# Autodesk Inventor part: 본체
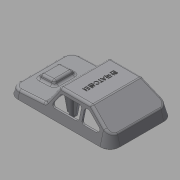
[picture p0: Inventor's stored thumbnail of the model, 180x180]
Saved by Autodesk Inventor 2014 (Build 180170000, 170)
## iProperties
Created: 2015-05
Part Number: 본체
Material: Generic
Document SubType Name: Modeling
Designer: Administrator
Density: 1 g/cm^3
Appearance: Default
Author: Administrator
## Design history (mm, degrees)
sketch "스케치1"
  geometry: L1 (-49, -38)-(49, -38); L2 (61, -26)-(61, 26); L3 (49, 38)-(-49, 38); L4 (-61, 26)-(-61, -26); L5 (-61, -38)-(61, 38); L6 (61, -38)-(-61, 38); A1 r 12 centre (-49, 26) between (-49, 38) and (-61, 26); A2 r 12 centre (-49, -26) between (-61, -26) and (-49, -38); A3 r 12 centre (49, -26) between (49, -38) and (61, -26); A4 r 12 centre (49, 26) between (61, 26) and (49, 38); 3 further points
  constraints: 12 end point, 8 point on circle, 8 point on line, 8 tangent, 4 centre point, 3 equal radius, 3 midpoint, 2 parallel, 1 coincident, 1 horizontal, 1 perpendicular
  dimensions: "d0" = 122 distance of L5.end L6.end; "d1" = 76 distance of L6.start L5.end; "d2" = 12 radius of A1
extrude "돌출1" new body sketch "스케치1" distance "d3" = 30; taper "d4" = -15 deg
sketch "스케치2"
  geometry: L1 (49, 30)-(-49, 30) reference; L2 (-61, 0)-(-52.962, 30) reference; L3 (49, 0)-(-49, 0) reference; L4 (-61, 0)-(-49, 0) reference; L5 (-52.962, 30)-(-49, 30) reference; L6 (-31, 30)-(-61, 10); L7 (-61, 10)-(-61, 30); L8 (-61, 30)-(-31, 30); 1 further point
  constraints: 6 end point, 2 perpendicular, 1 collinear, 1 vertical alignment
  dimensions: "d5" = 20 distance of L6.end L7.end; "d6" = 30 distance of L7.end L6.start
extrude "돌출2" cut sketch "스케치2" stored distance "d7" = 30; taper "d8" = 0 deg
sketch "스케치3"
  geometry: L1 (49, 0)-(61, 0) reference; L2 (61, 0)-(52.962, 30) reference; L3 (49, 30)-(-31, 30) reference; L4 (49, 30)-(52.962, 30) reference; L5 (49, 0)-(-49, 0) reference; L6 (61, 8)-(19, 10.201); L7 (19, 10.201)-(6.628, 30); L8 (6.628, 30)-(61, 30); L9 (61, 30)-(61, 8); 1 further point
  constraints: 8 end point, 1 collinear, 1 parallel, 1 perpendicular, 1 vertical alignment
  dimensions: "d10" = 125 deg angle of L7 L6; "d11" = 3 deg angle of L6 L5; "d12" = 8 distance of L6.start L1.end; "d13" = 42 horizontal distance of L6.end L6.start
extrude "돌출3" cut sketch "스케치3" stored distance "d14" = 30; taper "d15" = 0 deg
sketch "스케치4"
  geometry: L1 (-42.476, 9.267)-(-42.476, 61.267) reference; L2 (-31.476, 48.267)-(-11.476, 48.267); L3 (-11.476, 48.267)-(-11.476, 22.267); L4 (-11.476, 22.267)-(-31.476, 22.267); L5 (-31.476, 22.267)-(-31.476, 48.267); 3 further points
  constraints: 8 end point, 2 midpoint, 2 parallel, 1 horizontal, 1 horizontal alignment, 1 perpendicular
  dimensions: "d16" = 26 distance of L2.end L3.end; "d17" = 20 distance of L3.end L4.end; "d18" = 11 distance between parallel lines of L1 L5
extrude "돌출4" join sketch "스케치4" distance "d19" = 5; taper "d20" = -20 deg
fillet "모깎기1" dims "d21" = 3
fillet "모깎기2" dims "d22" = 3
fillet "모깎기3" dims "d23" = 3
fillet "모깎기4" dims "d24" = 3
feature "쉘1" dims "d25" = 2
sketch "스케치5"
  geometry: L1 (-49, 35.929)-(49, 35.929) reference; L2 (58.929, 26)-(58.929, -26) reference; L3 (49, -35.929)-(-49, -35.929) reference; L4 (-58.929, -26)-(-58.929, 26) reference; L5 (49, 36.929)-(-49, 36.929); L6 (-59.929, 26)-(-59.929, -26); L7 (-49, -36.929)-(49, -36.929); L8 (59.929, -26)-(59.929, 26); A1 r 9.929 centre (49, 26) between (58.929, 26) and (49, 35.929) reference; A2 r 9.929 centre (49, -26) between (49, -35.929) and (58.929, -26) reference; A3 r 9.929 centre (-49, -26) between (-58.929, -26) and (-49, -35.929) reference; A4 r 9.929 centre (-49, 26) between (-49, 35.929) and (-58.929, 26) reference; A5 r 10.929 centre (-49, 26) between (-49, 36.929) and (-59.929, 26); A6 r 10.929 centre (-49, -26) between (-59.929, -26) and (-49, -36.929); A7 r 10.929 centre (49, -26) between (49, -36.929) and (59.929, -26); A8 r 10.929 centre (49, 26) between (59.929, 26) and (49, 36.929); 1 further point
  constraints: 8 end point, 8 point on circle, 4 centre point, 7 other
  dimensions: "d26" = 1 distance between parallel lines of L5 L1
extrude "돌출5" join sketch "스케치5" distance "d27" = 1; taper "d28" = 0 deg
sketch "스케치6"
  geometry: L1 (18.172, 11.526)-(7.51, 28.59) reference; L2 (4.965, 30)-(-30.092, 30) reference; L3 (-31.756, 29.496)-(-50.664, 16.891) reference; L4 (10.362, 14.59)-(4.738, 23.59); L5 (2.194, 25)-(-17.77, 25); L6 (-20.77, 13)-(-20.77, 22); L7 (7.818, 10)-(-17.77, 10); L8 (-30.242, 24.496)-(-43.742, 15.496); L9 (-26.986, 25)-(-28.578, 25); L10 (-23.986, 22)-(-23.986, 13); L11 (-26.986, 10)-(-42.078, 10); A1 r 3 centre (7.818, 13) between (7.818, 10) and (10.362, 14.59); A2 r 3 centre (2.194, 22) between (4.738, 23.59) and (2.194, 25); A3 r 3 centre (-17.77, 22) between (-17.77, 25) and (-20.77, 22); A4 r 3 centre (-17.77, 13) between (-20.77, 13) and (-17.77, 10); A5 r 3 centre (-26.986, 13) between (-26.986, 10) and (-23.986, 13); A6 r 3 centre (-26.986, 22) between (-23.986, 22) and (-26.986, 25); A7 r 3 centre (-28.578, 22) between (-28.578, 25) and (-30.242, 24.496); A8 r 3 centre (-42.078, 13) between (-43.742, 15.496) and (-42.078, 10); 7 further points
  constraints: 16 end point, 16 point on circle, 16 tangent, 12 point on line, 8 centre point, 7 equal radius, 5 parallel, 3 perpendicular
  dimensions: "d29" = 5 distance between parallel lines of L2 L5; "d30" = 5 distance between parallel lines of L1 L4; "d31" = 34 distance of point (13.23, 10) point (-20.77, 10); "d32" = 15 distance of point (-20.77, 10) point (-20.77, 25); "d33" = 5 distance between parallel lines of L3 L8; "d34" = 5 distance between parallel lines of L2 L9; "d35" = 15 distance of point (-23.986, 25) point (-23.986, 10); "d36" = 28 distance of point (-23.986, 10) point (-51.986, 10); "d37" = 3 radius of A1
extrude "돌출6" cut sketch "스케치6" stored distance "d38" = 1; taper "d39" = 0 deg
node "작업 평면1"
sketch "스케치7"
  geometry: A1 r 4 centre (21, 0) between (25, 0) and (17, 0); A2 r 4 centre (10, 0) between (14, 0) and (6, 0); A3 r 4 centre (-10, 0) between (-6, 0) and (-14, 0); A4 r 4 centre (-21, 0) between (-17, 0) and (-25, 0); 4 further points
  constraints: 8 point on circle, 4 centre point, 4 horizontal alignment, 14 other
  dimensions: "d41" = 8 diameter of A1; "d42" = 8 diameter of A2; "d43" = 8 diameter of A3; "d44" = 8 diameter of A4; "d45" = 10 distance of A2.centre point (0, 0); "d46" = 20 distance of A3.centre A2.centre; "d47" = 11 distance of A2.centre A1.centre; "d48" = 11 distance of A4.centre A3.centre
extrude "돌출7" join sketch "스케치7" stored distance "d49" = 1; taper "d50" = 0 deg
chamfer "모따기1" distance "d51" = 1; stored, may be unused: second distance "d52" = 2, angle "d53" = 45 deg
sketch "스케치8"
  geometry: C1 r 3 at (-40, 0); C2 r 3 at (40, 0); C3 r 3 at (0, 22); C4 r 3 at (0, -22); 1 further point
  constraints: 4 centre point, 2 horizontal alignment, 2 vertical alignment
  dimensions: "d54" = 6 diameter of C1; "d55" = 6 diameter of C2; "d56" = 6 diameter of C3; "d57" = 6 diameter of C4; "d58" = 40 distance of point (0, 0) C1.centre; "d59" = 40 distance of C2.centre point (0, 0); "d60" = 22 distance of C3.centre point (0, 0); "d61" = 22 distance of point (0, 0) C4.centre
extrude "돌출8" join sketch "스케치8" stored distance "d62" = 1; taper "d63" = 2 deg
node "작업 평면2"
sketch "스케치9"
  geometry: L1 (-45, -1)-(-35, -1); L2 (-35, -1)-(-35, 1); L3 (-35, 1)-(-45, 1); L4 (-45, 1)-(-45, -1); L5 (-45, -1)-(-35, 1); L6 (-35, -1)-(-45, 1); L7 (-5, 21)-(5, 21); L8 (5, 21)-(5, 23); L9 (5, 23)-(-5, 23); L10 (-5, 23)-(-5, 21); L11 (-5, 21)-(5, 23); L12 (5, 21)-(-5, 23); L13 (35, -1)-(45, -1); L14 (45, -1)-(45, 1); L15 (45, 1)-(35, 1); L16 (35, 1)-(35, -1); L17 (35, -1)-(45, 1); L18 (45, -1)-(35, 1); L19 (-5, -23)-(5, -23); L20 (5, -23)-(5, -21); L21 (5, -21)-(-5, -21); L22 (-5, -21)-(-5, -23); L23 (-5, -23)-(5, -21); L24 (5, -23)-(-5, -21); C1 r 3 at (-40, 0) reference; C2 r 3 at (0, 22) reference; C3 r 3 at (40, 0) reference; C4 r 3 at (0, -22) reference; 1 further point
  constraints: 48 end point, 8 midpoint, 8 parallel, 4 horizontal, 4 perpendicular
  dimensions: "d65" = 10 distance of L1.start L1.end; "d66" = 2 distance of L1.end L2.end; "d67" = 10 distance of L7.start L7.end; "d68" = 2 distance of L7.end L8.end; "d69" = 10 distance of L19.start L19.end; "d70" = 2 distance of L19.end L20.end; "d71" = 10 distance of L13.start L13.end; "d72" = 2 distance of L13.end L14.end
extrude "돌출9" join sketch "스케치9" stored distance "d73" = 1; taper "d74" = 2.5 deg
sketch "스케치11"
  geometry: L1 (45, 2)-(45.429, 11.82) reference; L2 (35, 2)-(34.546, 12.39) reference; L3 (43, 0)-(43.07, 2) reference; L4 (37, 0)-(36.93, 2) reference; L5 (46.675, 11.755)-(34.533, 12.391) reference; L6 (47.906, 9.978)-(47.579, 11.049) reference; L7 (45, 2)-(46.72, 11.753); L8 (45.429, 11.82)-(46.72, 11.753); L9 (-49, 0)-(49, 0) reference; L10 (35, 2)-(33.155, 12.463); L11 (34.546, 12.39)-(33.155, 12.463); A1 r 1 centre (46.623, 10.756) between (47.579, 11.049) and (46.675, 11.755) reference; A2 r 5 centre (52.688, 11.44) between (47.906, 9.978) and (52.426, 6.447) reference; 1 further point
  constraints: 8 end point, 3 collinear, 1 point on line
  dimensions: "d76" = 80 deg angle of L7 L9; "d82" = 80 deg angle of L10 L9
extrude "돌출10" join sketch "스케치11" stored distance "d77" = 1; taper "d78" = 0 deg
sketch "스케치12"
  geometry: L1 (-45, 2)-(-46.719, 11.752) reference; L2 (-45.429, 11.82)-(-45, 2) reference; L3 (-46.675, 11.755)-(-45.429, 11.82) reference; A1 r 1 centre (-46.623, 10.756) between (-46.675, 11.755) and (-46.719, 11.752) reference; 1 further point
extrude "돌출11" join sketch "스케치12" stored distance "d79" = 1; taper "d80" = 0 deg
extrude "돌출12" join sketch "스케치11" stored distance "d83" = 1; taper "d84" = 0 deg
extrude "돌출13" join sketch "스케치11" stored distance "d85" = 1; taper "d86" = 0 deg
sketch "스케치13"
  geometry: L1 (-45, 2)-(-45.69, 17.803) reference; L2 (-35, 2)-(-33.969, 25.617) reference; L3 (-35, 2)-(-37.098, 2) reference; L4 (-42.902, 2)-(-45, 2) reference; L5 (49, 0)-(-49, 0) reference; L6 (-49.555, 15.226)-(-30.646, 27.832) reference; L7 (-45, 2)-(-47.566, 16.552); L8 (-35, 2)-(-30.426, 27.943); L9 (-30.092, 28)-(4.965, 28) reference; A1 r 1 centre (-30.092, 27) between (-30.092, 28) and (-30.646, 27.832) reference; 1 further point
  constraints: 4 end point, 1 point on circle, 1 point on line
  dimensions: "d87" = 80 deg angle of L8 L5; "d88" = 80 deg angle of L7 L5
extrude "돌출14" join sketch "스케치13" stored distance "d89" = 1; taper "d90" = 0 deg
extrude "돌출15" join sketch "스케치13" stored distance "d91" = 1; taper "d92" = 0 deg
extrude "돌출16" join sketch "스케치13" stored distance "d93" = 1; taper "d94" = 0 deg
extrude "돌출17" join sketch "스케치13" stored distance "d95" = 1; taper "d96" = 0 deg
node "작업 평면4"
sketch "스케치14"
  geometry: L1 (16.476, 10.466)-(5.813, 27.53) reference; L2 (4.965, 28)-(-30.092, 28) reference; L3 (-5, 2)-(-6.135, 28) reference; L4 (5, 2)-(6.095, 27.079) reference; L5 (-49, 0)-(49, 0) reference; L6 (5, 2)-(8.69, 22.927); L7 (-5, 2)-(-9.585, 28); 1 further point
  constraints: 4 end point, 2 point on line
  dimensions: "d98" = 80 deg angle of L6 L5; "d99" = 80 deg angle of L5 L7
extrude "돌출18" join sketch "스케치14" stored distance "d100" = 1; taper "d101" = 0 deg
extrude "돌출19" join sketch "스케치14" stored distance "d102" = 1; taper "d103" = 0 deg
extrude "돌출20" join sketch "스케치14" stored distance "d104" = 1; taper "d105" = 0 deg
extrude "돌출21" join sketch "스케치14" stored distance "d106" = 1; taper "d107" = 0 deg
node "작업 평면5"
sketch "스케치15"
  geometry: L1 (-5, 2)-(-6.135, 28) reference; L2 (5, 2)-(6.095, 27.079) reference; L3 (-30.092, 28)-(4.965, 28) reference; L4 (5.813, 27.53)-(16.476, 10.466) reference; L5 (49, 0)-(-49, 0) reference; L6 (-5, 2)-(-9.585, 28); L7 (5, 2)-(8.69, 22.927); 1 further point
  constraints: 4 end point, 2 point on line
  dimensions: "d109" = 80 deg angle of L7 L5; "d110" = 80 deg angle of L5 L6
extrude "돌출22" join sketch "스케치15" stored distance "d111" = 1; taper "d112" = 0 deg
extrude "돌출23" join sketch "스케치15" stored distance "d113" = 1; taper "d114" = 0 deg
extrude "돌출24" join sketch "스케치15" stored distance "d115" = 1; taper "d116" = 0 deg
extrude "돌출25" join sketch "스케치15" stored distance "d117" = 1; taper "d118" = 0 deg
sketch "스케치16"
  geometry: L1 (61, 26)-(61, -26) reference; 2 further points
  constraints: 1 horizontal alignment, 1 other
  dimensions: "d119" = 50 distance from line of L1 point (11, 0)
feature "엠보싱1" sketch "스케치16" dims "d120" = 0.5, "d121" = 0
sketch "스케치17"
  geometry: C1 r 3 at (0, 0) reference; C2 r 3 at (-40, 22) reference; C3 r 3 at (0, 44) reference; C4 r 3 at (40, 22) reference; 5 further points
  constraints: 4 coincident
hole "구멍1" sketch "스케치17" at (-40, 22), (0, 0), (0, 44), (40, 22) diameter "d122" = 3.242; stored, may be unused: countersink angle "d126" = 90 deg, drill point angle "d128" = 118 deg; dims "d123" = 9, "d124" = 4, "d125" = 2, "d127" = 11
node "솔리드1"
node "투영된 루프1"
node "투영된 루프2"
node "투영된 루프3"
node "투영된 루프4"
node "투영된 루프5"
node "투영된 루프6"
node "투영된 루프7"
other parameters: "d40" = -63, "d64" = 2, "d97" = -22, "d108" = 22
